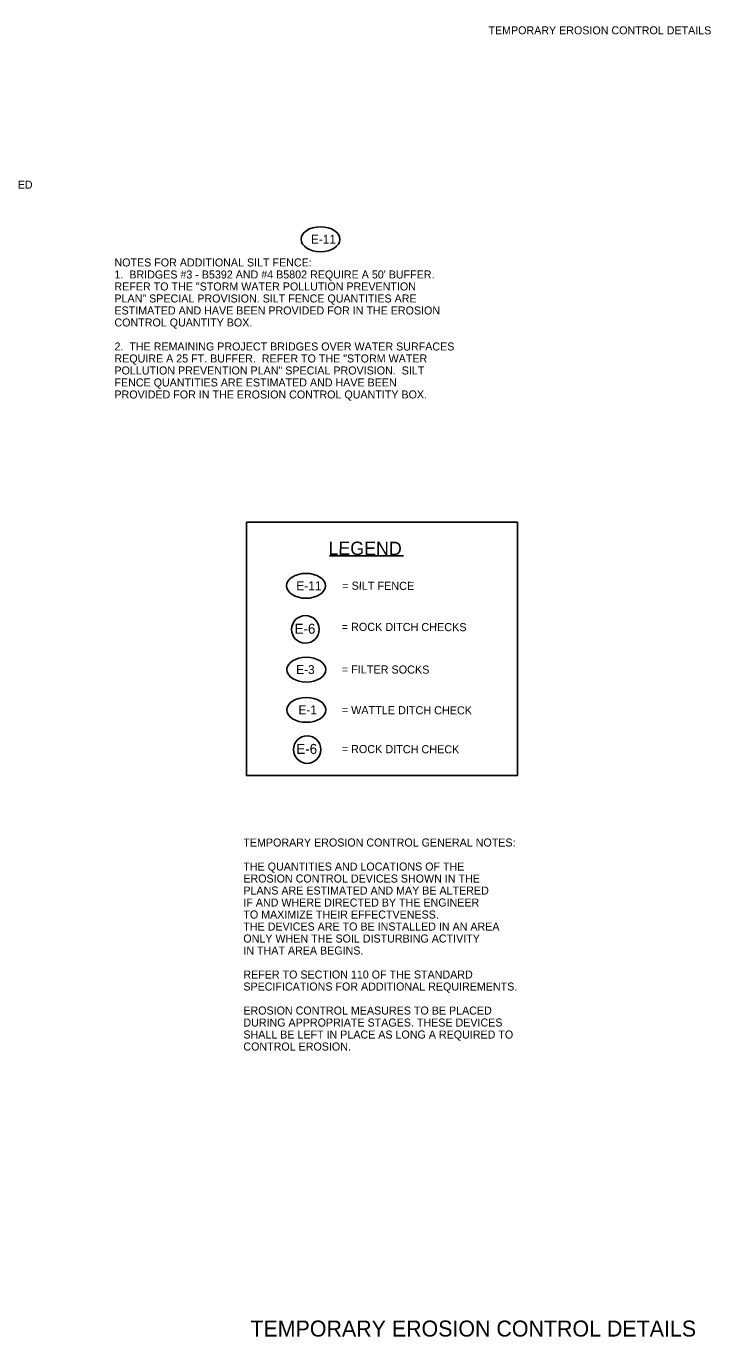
# Model space of a CAD drawing. Extents: x 1929624 to 1932070, y 596315 to 605533.
# Drawn here: x 1931556 to 1932070, y 604550 to 605533 of the extents above; entities that cross this region are included whole.
import ezdxf

# ---------------------------------------------------------------- set-up
doc = ezdxf.new("R2010")
doc.units = 0
for name, color, linetype in [('Default', 7, 'Continuous'), ('R_Border', 7, 'Continuous'), ('R_Border Prem', 7, 'Continuous')]:
    doc.layers.add(name, color=color, linetype=linetype)

msp = doc.modelspace()

# ---------------------------------------------------------------- linework, layer by layer
at = {"layer": 'R_Border'}
msp.add_line((1931783.66, 605135.66), (1931839.18, 605135.66), dxfattribs=at)
msp.add_lwpolyline([(1931721.23, 605160.73), (1931924.62, 605160.73), (1931924.62, 604970.79), (1931721.23, 604970.79)], close=True, dxfattribs=at)
for centre in [(1931765.53, 605080.41), (1931766.85, 604990.28)]:
    msp.add_circle(centre, 10.32, dxfattribs=at)
for centre in [(1931776.88, 605373), (1931765.98, 605113.09), (1931766.21, 605050.22), (1931766.21, 605020.05)]:
    msp.add_ellipse(centre, major_axis=(14.6, 0), ratio=0.638788, dxfattribs=at)

# ---------------------------------------------------------------- texts
at = {"layer": 'Default'}
for s, p in [('IF AND WHERE DIRECTED', (1931459.23, 605410.92)), ('NOTES FOR ADDITIONAL SILT FENCE:', (1931622.28, 605352.59)), ("1.  BRIDGES #3 - B5392 AND #4 B5802 REQUIRE A 50' BUFFER.  ", (1931622.28, 605343.59)), ('REFER TO THE "STORM WATER POLLUTION PREVENTION', (1931622.28, 605334.59)), ('PLAN" SPECIAL PROVISION. SILT FENCE QUANTITIES ARE ', (1931622.28, 605325.59)), ('ESTIMATED AND HAVE BEEN PROVIDED FOR IN THE EROSION ', (1931622.28, 605316.59)), ('CONTROL QUANTITY BOX.', (1931622.28, 605307.59)), ('2.  THE REMAINING PROJECT BRIDGES OVER WATER SURFACES', (1931622.28, 605289.59)), ('REQUIRE A 25 FT. BUFFER.  REFER TO THE "STORM WATER', (1931622.28, 605280.59)), ('POLLUTION PREVENTION PLAN" SPECIAL PROVISION.  SILT', (1931622.28, 605271.59)), ('FENCE QUANTITIES ARE ESTIMATED AND HAVE BEEN', (1931622.28, 605262.59)), ('PROVIDED FOR IN THE EROSION CONTROL QUANTITY BOX.', (1931622.28, 605253.59))]:
    msp.add_text(s, height=6, dxfattribs=at).set_placement(p)
for s, height, p in [('LEGEND', 10, (1931782.82, 605136.29)), ('= SILT FENCE', 6.075, (1931793.19, 605110.16)), ('= ROCK DITCH CHECKS', 6.075, (1931792.75, 605079.33)), ('= FILTER SOCKS', 6.075, (1931792.86, 605047.41)), ('= WATTLE DITCH CHECK', 6.075, (1931792.81, 605016.92)), ('= ROCK DITCH CHECK', 6.075, (1931792.78, 604987.68))]:
    msp.add_text(s, height=height, rotation=359.82713, dxfattribs=at).set_placement(p)
at = {"layer": 'R_Border'}
for s, p in [('E-11', (1931769.66, 605369.73)), ('E-11', (1931758.76, 605109.82)), ('E-3', (1931758.6, 605046.95)), ('E-1', (1931760.3, 605016.77))]:
    msp.add_text(s, height=6.663, rotation=360, dxfattribs=at).set_placement(p)
for s, height, p in [('E-6 ', 7.499, (1931757.41, 605077.15)), ('E-6 ', 7.499, (1931758.73, 604987.02)), ('TEMPORARY EROSION CONTROL GENERAL NOTES:', 6, (1931718.99, 604917.58)), ('THE QUANTITIES AND LOCATIONS OF THE', 6, (1931718.99, 604899.58)), ('EROSION CONTROL DEVICES SHOWN IN THE ', 6, (1931718.99, 604890.58)), ('PLANS ARE ESTIMATED AND MAY BE ALTERED ', 6, (1931718.99, 604881.58)), ('IF AND WHERE DIRECTED BY THE ENGINEER ', 6, (1931718.99, 604872.58)), ('TO MAXIMIZE THEIR EFFECTVENESS. ', 6, (1931718.99, 604863.58)), ('THE DEVICES ARE TO BE INSTALLED IN AN AREA ', 6, (1931718.99, 604854.58)), ('ONLY WHEN THE SOIL DISTURBING ACTIVITY', 6, (1931718.99, 604845.58)), ('IN THAT AREA BEGINS.', 6, (1931718.99, 604836.58)), ('REFER TO SECTION 110 OF THE STANDARD ', 6, (1931718.99, 604818.58)), ('SPECIFICATIONS FOR ADDITIONAL REQUIREMENTS.', 6, (1931718.99, 604809.58)), ('EROSION CONTROL MEASURES TO BE PLACED', 6, (1931718.99, 604791.58)), ('DURING APPROPRIATE STAGES. THESE DEVICES', 6, (1931718.99, 604782.58)), ('SHALL BE LEFT IN PLACE AS LONG A REQUIRED TO ', 6, (1931718.99, 604773.58)), ('CONTROL EROSION.', 6, (1931718.99, 604764.58)), ('TEMPORARY EROSION CONTROL DETAILS', 12, (1931724.27, 604550.07))]:
    msp.add_text(s, height=height, dxfattribs=at).set_placement(p)
at = {"layer": 'R_Border Prem'}
msp.add_text('TEMPORARY EROSION CONTROL DETAILS ', height=6, rotation=359.99339, dxfattribs=at).set_placement((1931902.85, 605526.69))

doc.saveas('drawing.dxf')
